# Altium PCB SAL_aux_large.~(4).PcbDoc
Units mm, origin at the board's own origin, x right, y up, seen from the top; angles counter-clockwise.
Board outline 62 x 80 mm, 2 copper layers (Top Layer, Bottom Layer); 29 components, 48 nets, 142 pads, 3 vias.
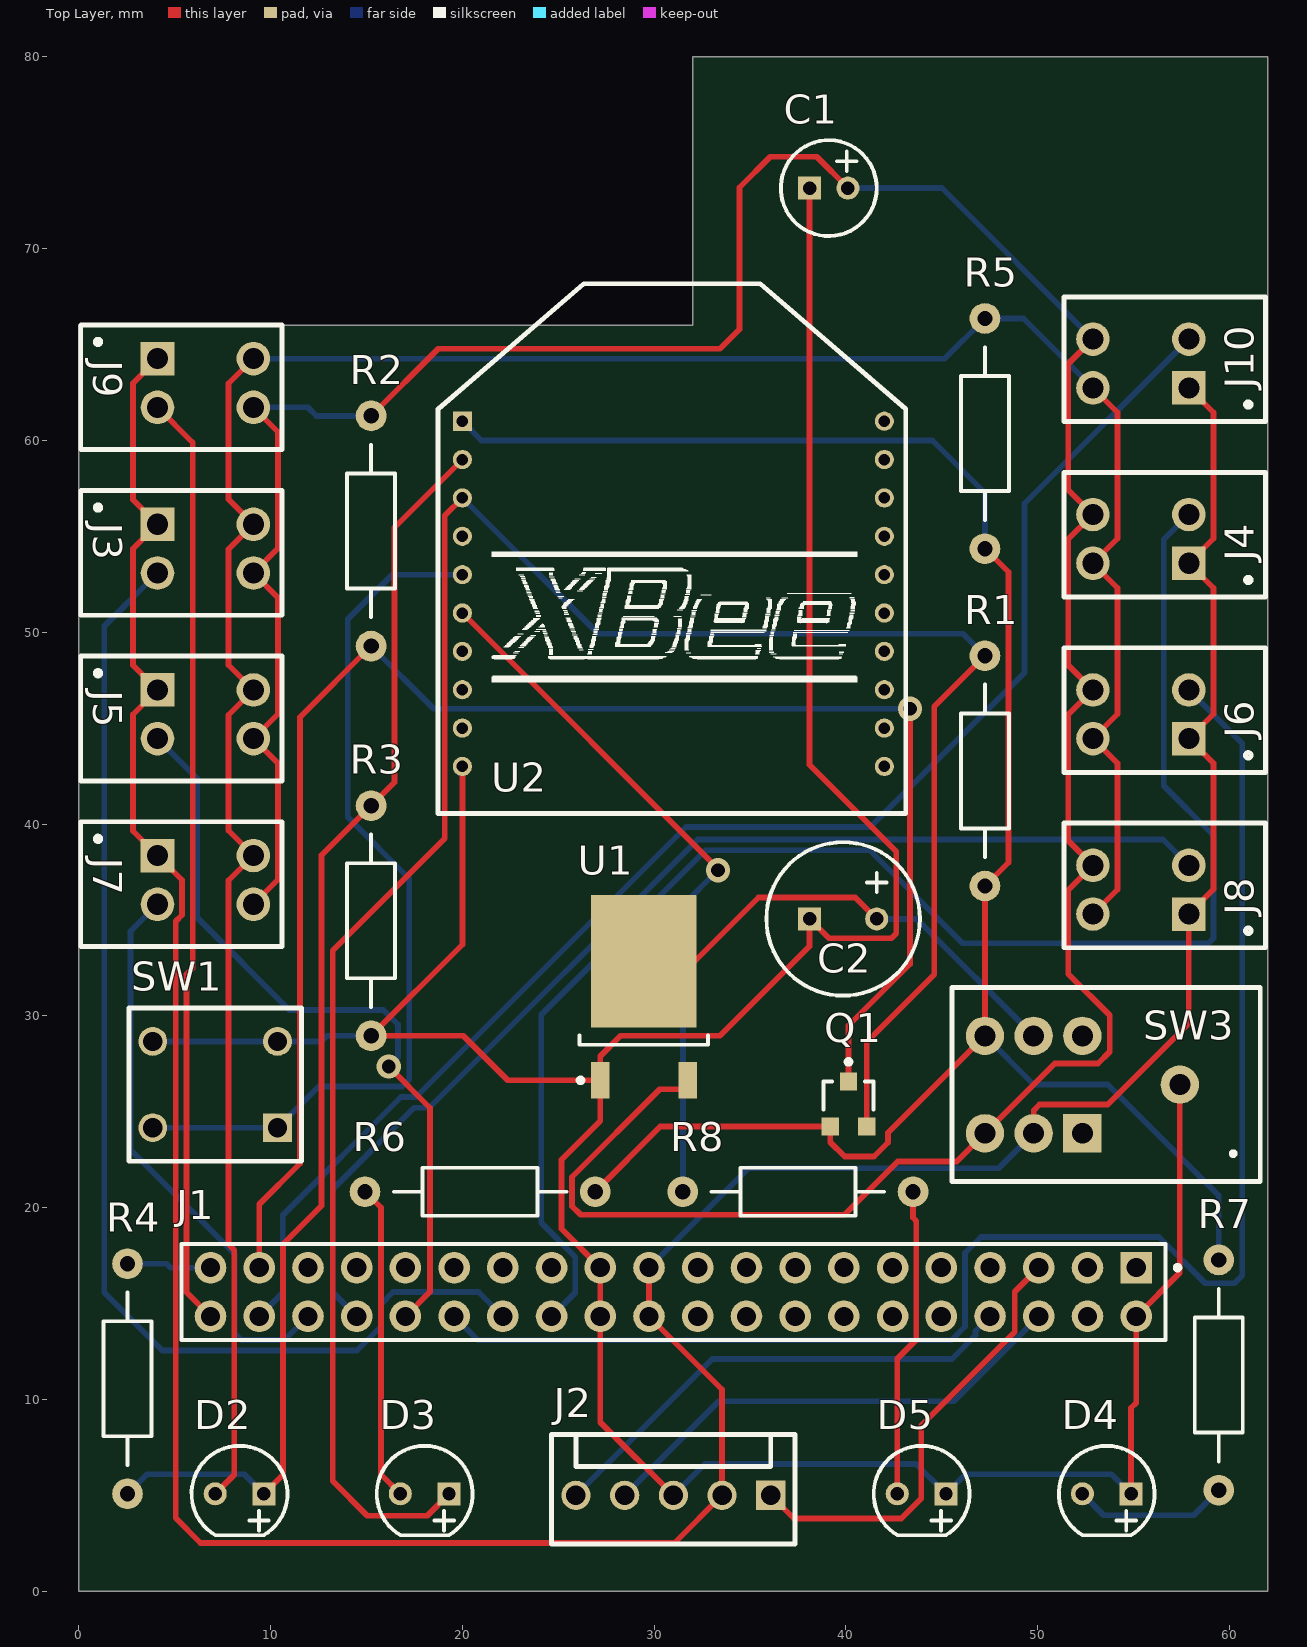
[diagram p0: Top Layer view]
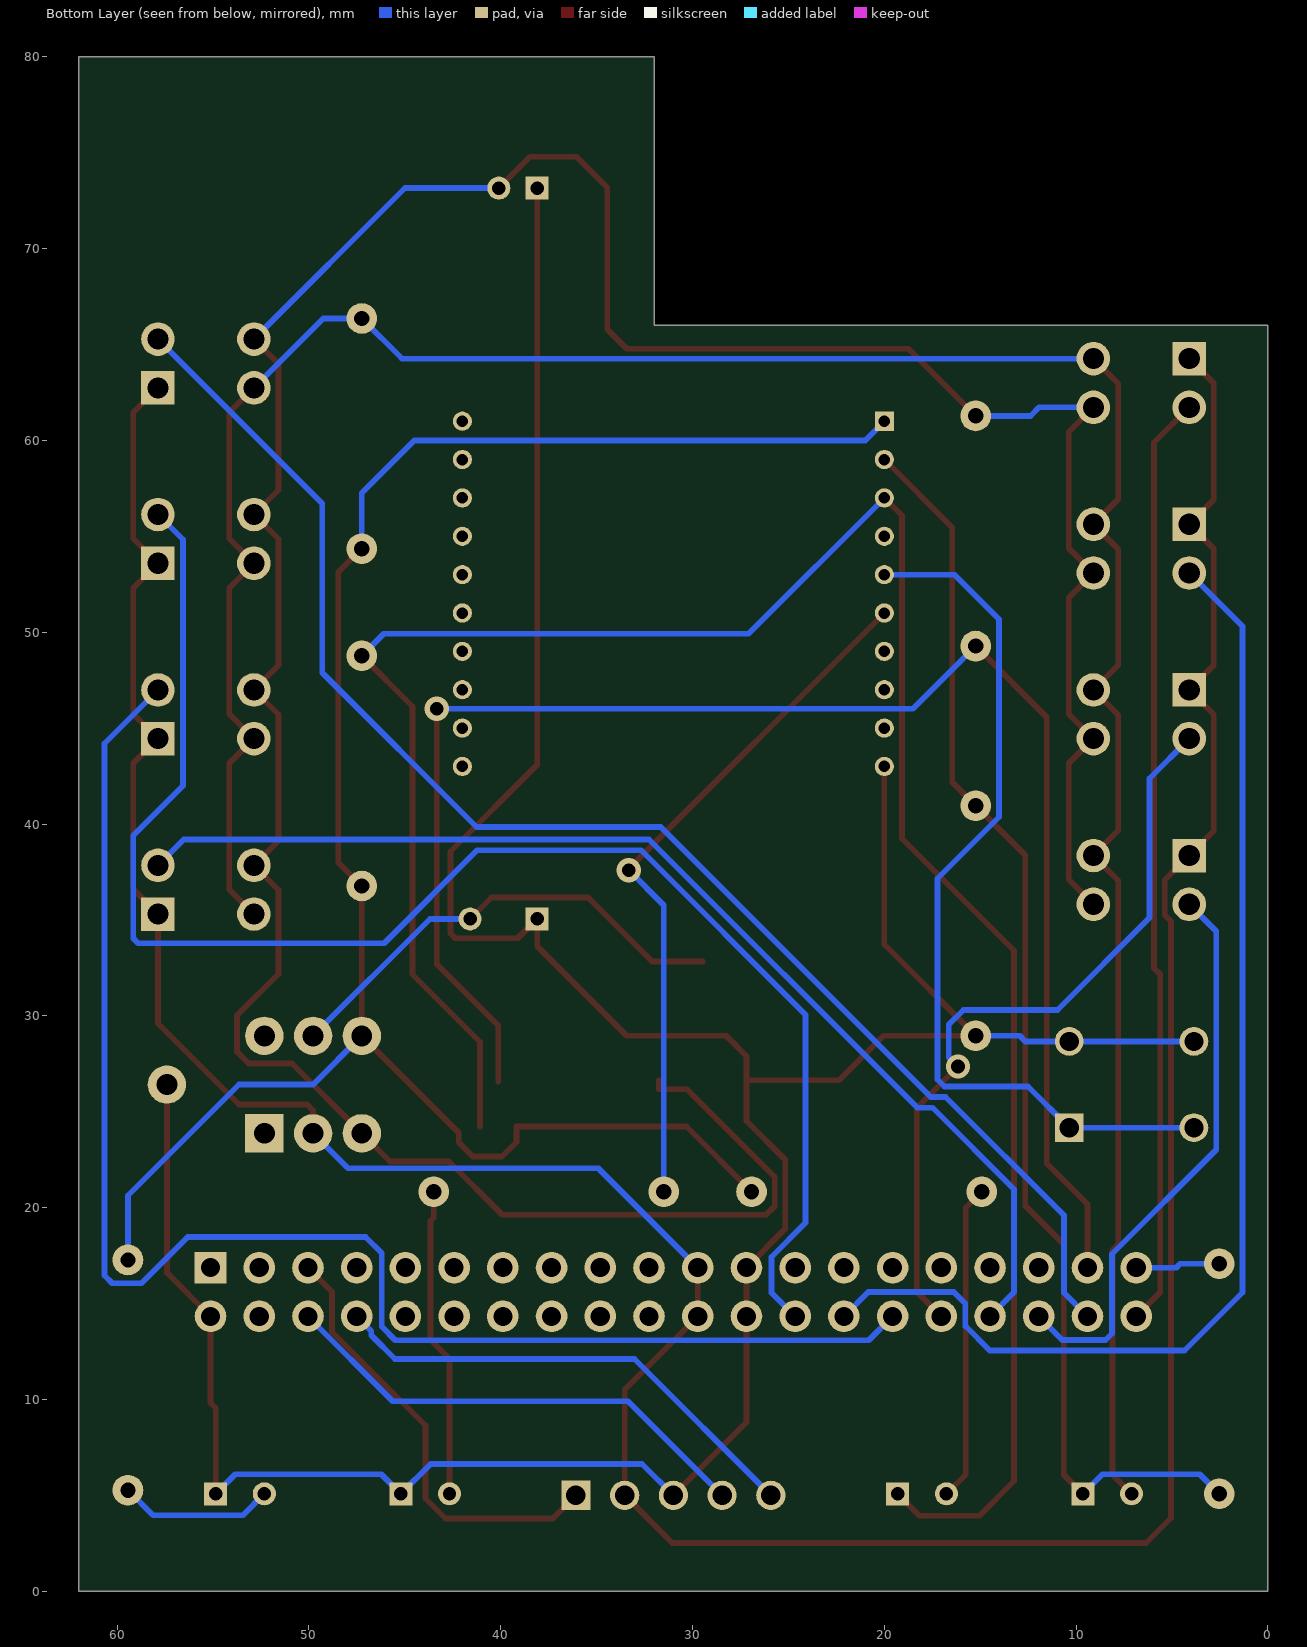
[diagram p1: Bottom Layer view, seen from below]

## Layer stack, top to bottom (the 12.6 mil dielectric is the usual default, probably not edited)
Top Layer: signal copper 0.0356
Dielectric: dielectric 0.32, FR-4, Dk 4.8
Bottom Layer: signal copper 0.0356

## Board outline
0,0 62,0 62,80 32,80 32,66 0,66

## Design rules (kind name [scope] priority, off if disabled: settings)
Clearance [All] p1: gap=0.254
PolygonConnect [All] p1: connectstyle=Relief reliefconductorwidth=0.254 reliefentries=4 polygonreliefangle="90 Angle"
RoomDefinition SAL_aux [InComponentClass('SAL_aux')] p1: confinementstyle=ConfineIn formatcopy=TRUE lockcomponents=FALSE outline 0,0 62,0 62,80 0,80
RoutingVias [All] p1: holewidth=0.711 width=1.27 viastyle="Through Hole" minholewidth=0.711 minwidth=1.27 maxholewidth=0.711 maxwidth=1.27
SilkscreenOverComponentPads [All] p1: minsilkscreentomaskgap=0.254
SolderMaskExpansion [All] p1: expansion=0.102
TestPointUsage [All] p1: valid=0 allowmultiple=FALSE
Testpoint [All] p1: side=15 testpointundercomponent=TRUE minsize=1.016 maxsize=2.54 preferedsize=1.524 minholesize=0 maxholesize=1.016 preferedholesize=0.813 testpointgrid=0.025 style=1023 order=0123456789
Width [All] p1: maxlimit=1 minlimit=0.254 preferedwidth=0.3 checkconnectedcopper=TRUE
23 further rules are at their usual default settings.

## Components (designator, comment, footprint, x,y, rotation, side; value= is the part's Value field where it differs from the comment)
C1 "10 uF" "PANASONIC ECA1HAM100X" 38.1,73.152 r0 top
C2 "100 uF" "PANASONIC ECA1HAM101X" 38.1,35.052 r0 top
D2 "Yellow" "VISHAY TLLR4401" 7.112,5.08 r0 top
D3 "Red" "VISHAY TLLR4401" 16.764,5.08 r0 top
D4 "Green" "VISHAY TLLR4401" 52.324,5.08 r0 top
D5 "Blue" "VISHAY TLLR4401" 42.672,5.08 r0 top
J1 "SSW-120-01-G-D" "SAMTEC SSW-120-1-G-D" 31,15.6 r180 top
J2 "I2C Connector" "TYCO 640456-5" 31,5 r0 top
J3 "WAGO 234-502" "WAGO 234-502" 6.604,54.356 r270 top
J4 "WAGO 234-502" "WAGO 234-502" 55.372,54.864 r90 top
J5 "WAGO 234-502" "WAGO 234-502" 6.604,45.72 r270 top
J6 "WAGO 234-502" "WAGO 234-502" 55.372,45.72 r90 top
J7 "WAGO 234-502" "WAGO 234-502" 6.604,37.084 r270 top
J8 "WAGO 234-502" "WAGO 234-502" 55.372,36.576 r90 top
J9 "WAGO 234-502" "WAGO 234-502" 6.604,62.992 r270 top
J10 "WAGO 234-502" "WAGO 234-502" 55.372,64.008 r90 top
Q1 "BSS138" SOT23 40.132,25.4 r0 top
R1 "10K" Resistência 47.244,48.768 r270 top
R2 "10K" Resistência 15.24,49.276 r90 top
R3 "10K" Resistência 15.24,28.956 r90 top
R4 "10K" Resistência 2.54,5.08 r90 top
R5 "1K" Resistência 47.244,54.356 r90 top
R6 "1K" Resistência 26.924,20.828 r180 top
R7 "1K" Resistência 59.436,17.272 r270 top
R8 "1K" Resistência 31.496,20.828 r0 top
SW1 "OMRON B3F-1002" "OMRON B3F-1002" 7.112,26.416 r0 top
SW3 "MULTICOMP 2AD1T2A2M7RE" "MULTICOMP 2AD1T2A2M7RE" 49.784,26.416 r90 top
U1 "LM1117DT-3.3" TD03B_N 29.464,30.988 r90 top
U2 "XBee" XBee 31,51 r0 top

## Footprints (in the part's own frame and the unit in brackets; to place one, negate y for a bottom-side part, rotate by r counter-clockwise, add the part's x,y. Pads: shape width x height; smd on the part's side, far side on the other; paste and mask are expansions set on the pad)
"MULTICOMP 2AD1T2A2M7RE" [mm] "Switch, DPDT ON-ON"
  rect 2x2 hole 1.09: 1(-2.54,-2.54)
  round 2 hole 1.09: 2(-2.54,0) 3(-2.54,2.54) 4(2.54,-2.54) 5(2.54,0) 6(2.54,2.54) GND(0,-7.62)
  silkscreen extent -5.06,-11.81 5.05,4.25
"OMRON B3F-1002" [mm] "6.0mm Tactil Switch"
  rect 1.5x1.5 hole 1: 1(3.25,-2.25)
  round 1.5 hole 1: 2(-3.25,-2.25) 3(3.25,2.25) 4(-3.25,2.25)
  silkscreen extent -4.5,-4 4.5,4
"PANASONIC ECA1HAM100X" [mm]
  rect 1.2x1.2 hole 0.7: 1(0,0)
  round 1.2 hole 0.7: 2(2,0)
  silkscreen extent -1.5,-2.5 3.5,2.5
"PANASONIC ECA1HAM101X" [mm]
  rect 1.2x1.2 hole 0.7: 1(0,0)
  round 1.2 hole 0.7: 2(3.5,0)
  silkscreen extent -2.25,-4 5.75,4
Resistência [mm]
  round 1.6 hole 0.8: 1(0,0) 2(12,0)
  silkscreen extent 1.5,-1.25 10.5,1.25
"SAMTEC SSW-120-1-G-D" [mm]
  rect 1.65x1.65 / inner round 1.65 / far side rect 1.65x1.65 hole 1 mask+0: 1(-24.13,-1.27)
  round 1.65 hole 1 mask+0: 2(-24.13,1.27) 3(-21.59,-1.27) 4(-21.59,1.27) 5(-19.05,-1.27) 6(-19.05,1.27) 7(-16.51,-1.27) 8(-16.51,1.27) 9(-13.97,-1.27) 10(-13.97,1.27) 11(-11.43,-1.27) 12(-11.43,1.27) 13(-8.89,-1.27) 14(-8.89,1.27) 15(-6.35,-1.27) 16(-6.35,1.27) 17(-3.81,-1.27) 18(-3.81,1.27) 19(-1.27,-1.27) 20(-1.27,1.27) 21(1.27,-1.27) 22(1.27,1.27) 23(3.81,-1.27) 24(3.81,1.27) 25(6.35,-1.27) 26(6.35,1.27) 27(8.89,-1.27) 28(8.89,1.27) 29(11.43,-1.27) 30(11.43,1.27) 31(13.97,-1.27) 32(13.97,1.27) 33(16.51,-1.27) 34(16.51,1.27) 35(19.05,-1.27) 36(19.05,1.27) 37(21.59,-1.27) 38(21.59,1.27) 39(24.13,-1.27) 40(24.13,1.27)
  silkscreen extent -26.41,-2.5 25.65,2.5
SOT23 [mm] "SOT-23; 3 Leads; Body 3.1 x 2.5 mm, inc. leads (LxW max), Alternate Lead Configuration"
  rect 0.9x0.95 smd: 1(0,1.175) 2(0.95,-1.175) 3(-0.95,-1.175)
  silkscreen extent -1.3,-0.3 1.3,2.32
TD03B_N [mm] "D-PAK, 4-Leads, Body 6.1x6.6mm, Pitch 2.29mm, Lead Span 9.7mm, IPC Medium Density"
  rect 1.9x0.95 smd: 1(-4.35,2.28) 3(-4.35,-2.28)
  rect 6.9x5.5 smd: 4(1.85,0)
  silkscreen extent -4.47,-3.35 -2,3.43
"TYCO 640456-5" [mil] "I2C Connector"
  rect 60x60 hole 40.16: 1(200,0)
  round 60 hole 40.16: 2(100,0) 3(0,0) 4(-100,0) 5(-200,0)
  silkscreen extent -250,-100 250,125
"VISHAY TLLR4401" [mm] "3mm LED"
  round 1.2 hole 0.7: 1(0,0)
  rect 1.2x1.2 hole 0.7: 2(2.54,0)
  silkscreen extent -1.23,-2.17 3.77,2.5
"WAGO 234-502" [mm]
  rect 1.75x1.75 hole 1.1: 1(-1.27,-2.5)
  round 1.75 hole 1.1: 2(-1.27,2.5) 3(1.27,-2.5) 4(1.27,2.5)
  silkscreen extent -3.03,-6.5 3.47,4
XBee [mm] "ZigBee device"
  rect 1x1 hole 0.6: 1(-11,10)
  round 1 hole 0.6: 2(-11,8) 3(-11,6) 4(-11,4) 5(-11,2) 6(-11,0) 7(-11,-2) 8(-11,-4) 9(-11,-6) 10(-11,-8) 11(11,-8) 12(11,-6) 13(11,-4) 14(11,-2) 15(11,0) 16(11,2) 17(11,4) 18(11,6) 19(11,8) 20(11,10)
  silkscreen extent -12.26,-10.44 12.12,17.17

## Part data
C1: library part "PANASONIC ECA1HAM100X"
C2: library part "PANASONIC ECA1HAM101X"
D2 D3 D4 D5: library part "VISHAY TLLG4401", "Green LED PCB 3mm"
J1: library part "SAMTEC SSW-120-01-G-D"
J2: library part "TYCO 640456-5"
Q1: "N-Channel Enhancement Mode Vertical DMOS FET"
R1 R2 R3 R4 R5 R6 R7 R8: library part Resistência
SW1: "6.0mm Tact Switch"
U1: "800mA Low-Dropout Linear Regulator"

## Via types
v1: diameter 1.27, hole 0.711, Top Layer to Bottom Layer, 3 vias

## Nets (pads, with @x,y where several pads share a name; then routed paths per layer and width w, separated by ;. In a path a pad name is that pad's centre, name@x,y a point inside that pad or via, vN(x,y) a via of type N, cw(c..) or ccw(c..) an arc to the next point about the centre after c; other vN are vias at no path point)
1: D2.1 J3.2 J4.2 J5.2 J6.2 J7.2 J8.2 J9.2 J10.2 R5.2 | length 140.3
  Top Layer w0.3: D2.1 8.106,6.074 8.106,17.784 7.801,18.089 7.801,37.051 J7.2 7.801,39.657 7.801,45.687 J5.2 7.801,48.293 7.801,54.323 J3.2 7.801,56.929 7.801,62.959 J9.2 ; J8.2 54.156,36.59 54.156,43.166 J6.2 54.156,45.734 54.156,52.31 J4.2 54.156,54.878 54.156,61.454 J10.2
  Bottom Layer w0.3: J9.2 45.15,64.262 R5.2 49.254,66.356 J10.2
3.3V: Q1.3 R1.2 R5.1 R6.1 R7.1 SW3.6 U2.1 | length 102.9
  Top Layer w0.3: R6.1 30.321,24.225 Q1.3 39.182,23.411 39.932,22.661 41.456,22.661 42.193,23.397 42.193,23.905 SW3.6 R1.2 48.466,37.99 48.466,53.134 R5.1
  Bottom Layer w0.3: U2.1 21.001,59.999 44.504,59.999 47.244,57.259 R5.1 ; SW3.6 49.78,26.42 53.648,26.42 59.436,20.632 R7.1
"3.3V OUT": C2.2 SW3.5 U1.4 | length 24.7
  Top Layer w0.3: U1.4 32.101,32.838 35.436,36.174 40.478,36.174 C2.2
  Bottom Layer w0.3: C2.2 43.688,35.052 SW3.5
/INT: J1.20
/RESET: J1.5 J2.1 | length 23.4
  Top Layer w0.3: J2.1 37.291,3.789 42.878,3.789 43.92,4.83 43.92,8.64 48.797,13.517 48.797,15.617 J1.5
A0: J1.7
A4/LSDA: J1.1
A5/LSCL: J1.3
B5: J1.10
C0: J1.25
C1: J1.27
C2: J1.29
C5: J1.35
D0: J1.40 J9.3 | length 48.8
  Top Layer w0.3: J9.3 5.937,59.889 5.937,32.483 5.617,32.163 5.617,15.583 J1.40
D1: J1.38 J10.3 | length 77.1
  Bottom Layer w0.3: J1.38 10.639,15.559 10.639,19.599 16.806,25.767 17.58,25.767 31.658,39.845 41.267,39.845 49.305,47.883 49.305,56.711 J10.3
D2: J1.36 J7.3 | length 29.7
  Bottom Layer w0.3: J7.3 2.696,34.406 2.696,23.016 8.131,17.581 8.131,13.441 8.471,13.101 10.721,13.101 J1.36
D3: J1.34 J8.3 | length 59.9
  Bottom Layer w0.3: J1.34 13.237,15.583 13.237,20.96 17.49,25.213 18.289,25.213 32.272,39.196 56.522,39.196 J8.3
D4: J1.32 J5.3 | length 39.8
  Top Layer w0.3: v1(16.158,27.36) 18.317,25.201 18.317,15.617 J1.32
  Bottom Layer w0.3: J5.3 6.175,42.379 6.175,35.107 10.976,30.306 15.878,30.306 16.643,29.542 16.643,27.845 v1(16.158,27.36)
D5: J1.30 J6.3 | length 78.9
  Bottom Layer w0.3: J1.30 20.815,13.085 45.495,13.085 46.206,13.796 46.206,17.632 47.044,18.47 56.315,18.47 58.728,16.057 60.252,16.057 60.658,16.463 60.658,44.204 J6.3
D6: J1.28 J3.3 | length 63.2
  Bottom Layer w0.3: J3.3 1.324,50.306 1.324,15.574 4.351,12.547 14.502,12.547 15.777,13.822 15.777,14.99 16.386,15.6 20.84,15.6 J1.28
D7: J1.26 J4.3 | length 81.4
  Bottom Layer w0.3: J1.26 25.886,15.566 25.886,17.428 24.108,19.206 24.108,30.052 32.693,38.637 41.227,38.637 46.079,33.786 58.906,33.786 59.16,34.04 59.16,39.399 56.569,41.99 56.569,54.831 J4.3
DIN: D3.2 Q1.2 R1.1 U2.3 | length 119.1
  Top Layer w0.3: D3.2 18.165,3.941 15.04,3.941 13.237,5.744 13.237,33.405 19.079,39.247 19.079,56.079 U2.3 ; Q1.2 41.082,28.637 44.606,32.16 44.606,46.13 R1.1
  Bottom Layer w0.3: U2.3 27.085,49.915 46.097,49.915 R1.1
DOUT: D2.2 R3.2 R4.1 U2.2 | length 66.2
  Top Layer w0.3: D2.2 10.646,6.074 10.646,18.089 12.652,20.095 12.652,38.368 R3.2 16.462,42.178 16.462,55.462 U2.2
  Bottom Layer w0.3: R4.1 3.56,6.1 8.632,6.1 D2.2
EYEB: J1.19
EYEF: J1.9
EYEL: J1.13
EYER: J1.11
NetD3_1: D3.1 R6.2 | length 16.5
  Top Layer w0.3: R6.2 15.751,20.001 15.751,6.093 D3.1
NetD4_1: D4.1 R7.2 | length 8.1
  Bottom Layer w0.3: D4.1 53.438,3.966 58.13,3.966 R7.2
NetD5_1: D5.1 R8.2 | length 16.2
  Top Layer w0.3: D5.1 42.672,12.117 43.666,13.11 43.666,19.308 43.496,19.478 R8.2
PWM1/SERVOR: J1.18
PWM2/SERVOL: J1.16
PWM3: J1.14
PWM4: J1.12
RESET: SW1.1 SW1.2 U2.5 | length 46.7
  Bottom Layer w0.3: SW1.2 SW1.1 12.517,26.321 16.871,26.321 17.224,26.674 17.224,37.164 14.024,40.365 14.024,50.677 16.347,53 U2.5
RSSI: R8.1 U2.6 | length 36.5
  Top Layer w0.3: U2.6 33.328,37.672 v1(33.328,37.596)
  Bottom Layer w0.3: R8.1 31.496,35.764 v1(33.328,37.596)
RX: J1.39 R4.2 | length 4.4
  Bottom Layer w0.3: R4.2 4.575,17.08 4.785,16.87 J1.39
SCL: J1.31
SDA: J1.33
TX: J1.37 Q1.1 R2.1 | length 85
  Top Layer w0.3: J1.37 9.41,20.18 11.535,22.305 11.535,45.571 R2.1 ; Q1.1 40.132,29.49 43.336,32.694 v1(43.336,46.003)
  Bottom Layer w0.3: R2.1 18.513,46.003 v1(43.336,46.003)
US_B: J1.17
US_F: J1.15
V+: J1.4
VDD: J1.21 J1.22 J2.2 J3.1 J4.1 J5.1 J6.1 J7.1 J8.1 J9.1 J10.1 SW3.2 | length 178.2
  Top Layer w0.3: J9.1 2.823,62.981 2.823,56.907 J3.1 2.823,54.345 2.823,48.271 J5.1 2.823,45.709 2.823,39.635 J7.1 5.383,37.075 5.383,35.254 5.058,34.929 5.058,3.814 6.353,2.519 31.059,2.519 J2.2 33.54,10.52 J1.22 J1.21 ; SW3.2 49.784,25.071 50.092,25.379 53.648,25.379 57.872,29.603 J8.1 59.16,36.594 59.16,43.162 J6.1 59.16,45.738 59.16,52.306 J4.1 59.16,54.882 59.16,61.45 J10.1
  Bottom Layer w0.3: J1.21 34.911,22.051 47.959,22.051 SW3.2
"VDD OUT": C1.2 J3.4 J4.4 J5.4 J6.4 J7.4 J8.4 J9.4 J10.4 R2.2 SW3.3 U1.3 | length 170.3
  Top Layer w0.3: J7.4 10.392,37.102 10.392,43.162 J5.4 10.392,45.738 10.392,51.798 J3.4 10.392,54.374 10.392,60.434 J9.4 ; R2.2 18.738,64.774 33.43,64.774 34.446,65.79 34.446,73.181 36.046,74.782 38.47,74.782 C1.2 ; U1.3 31.744,26.166 30.292,26.166 25.72,21.594 25.72,20.07 26.166,19.624 39.918,19.624 42.701,22.407 45.775,22.407 SW3.3 50.88,27.512 53.14,27.512 53.75,28.122 53.75,30.027 51.591,32.186 51.591,36.565 J8.4 51.591,39.127 51.591,45.709 J6.4 51.591,48.271 51.591,54.853 J4.4 51.591,57.415 51.591,63.997 J10.4
  Bottom Layer w0.3: J9.4 11.941,61.722 12.387,61.276 R2.2 ; C1.2 44.998,73.152 J10.4
VSS: C1.1 C2.1 D4.2 D5.2 J1.2 J1.23 J1.24 J2.3 R3.1 SW1.3 SW1.4 SW3.GND U1.1 U2.10 | length 175.5
  Top Layer w0.3: U2.10 20,33.716 R3.1 20.044,28.956 22.362,26.638 U1.1 ; J2.3 27.19,8.81 J1.24 J1.23 25.166,18.894 25.166,22.5 27.184,24.518 U1.1 ; C1.1 38.1,43.086 42.624,38.561 42.624,34.294 42.37,34.04 39.112,34.04 C2.1 38.1,33.63 33.43,28.96 28.248,28.96 27.184,27.896 U1.1 ; D4.2 54.864,9.554 55.13,9.82 J1.2 57.404,16.604 SW3.GND
  Bottom Layer w0.3: SW1.4 SW1.3 12.652,28.666 12.942,28.956 R3.1 ; J2.3 32.638,6.638 43.654,6.638 D5.2 46.232,6.1 53.844,6.1 D4.2
XAXIS: J1.8 J2.5 | length 25.6
  Bottom Layer w0.3: J2.5 33.028,12.108 45.52,12.108 46.753,13.341 46.753,13.573 J1.8
YAXIS: J1.6 J2.4 | length 25.5
  Bottom Layer w0.3: J2.4 33.37,9.91 45.63,9.91 J1.6
pads on no net: SW3.1 SW3.4 U2.4 U2.7 U2.8 U2.9 U2.11 U2.12 U2.13 U2.14 U2.15 U2.16 U2.17 U2.18 U2.19 U2.20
